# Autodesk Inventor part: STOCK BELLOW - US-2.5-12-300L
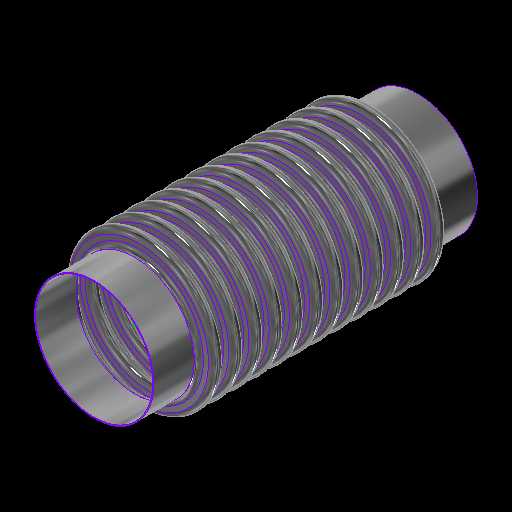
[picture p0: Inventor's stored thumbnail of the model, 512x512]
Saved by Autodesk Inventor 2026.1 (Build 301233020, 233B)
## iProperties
Category: 24 GA (0.024 THICK)
RuleStatus: InUse
Created: 2024-01
Part Number: STOCK BELLOW - US-2.5-12-300L
Project: =STOCK BELLOWS: <Stock Number><SFILL>
Material: ASTM A240-304
Description: =STOCK BELLOWS: <Stock Number>, <SID_> I.D., <SOD_> O.D., <SPLY_> PLY, <Category>, <SNET_CONS> CONS.<PITCH_><STANGENT_> TANGENT<SFILL>
Document SubType Name: Sheet Metal
Designer: GS
Stock Number: U.S-2.5-12-300L
Surface Area: 1910.87 cm^2
Volume: 57.9833 cm^3
Sheet Metal Rule: Default
Appearance: STAINLESS STEEL
Mass: 467.188 g
Density: 8.05729 g/cm^3
THK: 0.036
ID: 3.500
OD: 4.250
CONS_: 2
PITCH: 0.500
TANGENT: 0.500
BELLOWS_UPSET: 0.000
d79: 1.000
d82: 1.000
d83: 26.000
d84: 24.000
d174: 8
d214: 8
STHK_: 0.024
SID_: 2.900
SOD_: 3.700
SPITCH_: 0.500
STANGENT__: 1.000
SBELLOWS_UPSET_: 0.000
SDIFF_TAN: 1.000
d252: 2
d275: 2
d287: 0.050
d289: 0.500
d290: 0.000
SOD_NECK: 2 15/16
PLY: 1
PSET: 4.178
PBAR: 1.035
COUNTER: 1.500
NET_TUBE: 3.071
CONS: 2
S_CONS: 0
NET_CONS: 2
ID_M: 88.90 mm
OD_M: 107.95 mm
THK_M: 0.91 mm
ID_U: 3.500 in
OD_U: 4.250 in
THK_U: 0.036 in
TANGENT2: 0.500
TAN_TO_TAN: 1.000 in
d80: 2.571
d81: 10
SID: 2.375
SCONS_: 12
SPITCH: 0.250
STANGENT_: 1.000
SBELLOWS_UPSET: 0.000
SNET_CONS: 12
SS_CONS: 0
SCONS: 8
d190: 8
d191: 1
d192: 1
d193: 8
d194: 0
SIZE: 2.50
PRESSURE: 300
d230: 8
STANGENT: 4.000
SPLY_: 1
d233: 8
d234: 0
d263: 2
d265: 1
d268: 2
d269: 0
d286: 2
d288: 1
d291: 2
d292: 0
SREROLL: 0.750
BLETP: 1.000 ul
PRES_Copy: 85
MATTABLE: 20 GA (0.036 THICK)
PART_NUMBER: U.S-2.5-12-300L
PITCH_: =, <SPITCH_> PITCH,
CFILL: .
SFILL: .
MESH: ,
COMP: 0.89
EXT: 0.45
LAT: 0.52
ANG: 573
ASR: 961
LSR: 436
ANSR: 35
PRES: 300
COMPM: 8.9
EXTM: 4.45
LATM: 5.20
ASRM: 168.300
PRESM: 20.684
LSRM: 76.357
ANSRM: 6.13
TEMPMIN: 20
TEMPMAX: 800
TEMPMINM: -7
TEMPMAXM: 427
WEIGHTM: 0.467
WEIGHT: 1.030
Author: GS
Keywords: 20 GA (0.036 THICK)
Comments: =STOCK BELLOW - <STOCK NUMBER>
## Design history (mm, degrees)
sketch "Sketch2"
  geometry: L1 (0, -177.245)-(0, 562.856) reference; L2 (45.364, 0)-(44.45, 0); L3 (48.082, -2.718)-(50.343, -2.718); L4 (48.082, -3.632)-(50.343, -3.632); L5 (50.343, -9.982)-(48.082, -9.982); L6 (50.343, -9.068)-(48.082, -9.068); L7 (45.364, -12.7)-(44.45, -12.7); L8 (48.082, 0)-(48.082, -12.7); L9 (50.343, -6.35)-(53.975, -6.35); L10 (44.45, 0)-(44.45, -12.7); L11 (20.376, 102.841)-(20.376, 101.926); L12 (58.262, 457.127)-(58.262, 349.177); L13 (58.262, 444.427)-(58.262, 336.477); L14 (93.133, -58.817)-(93.133, -71.517); L15 (118.746, -66.401)-(118.746, -66.401); L16 (50.343, -9.068)-(50.343, -9.982); L17 (48.082, -9.068)-(48.082, -9.982); L18 (48.082, -9.525)-(50.343, -9.525); L19 (53.975, 0)-(53.975, -12.7); L20 (-50.343, -9.068)-(-50.343, -9.982); L21 (-50.343, -2.718)-(-48.082, -2.718); L22 (-50.343, -3.632)-(-48.082, -3.632); L23 (-48.082, -9.068)-(-50.343, -9.068); L24 (-50.343, -9.525)-(-48.082, -9.525); L25 (-48.082, -9.982)-(-50.343, -9.982); L26 (-48.082, -9.068)-(-48.082, -9.982); L27 (-44.45, 0.653)-(-44.45, -12.047); L28 (-48.082, -6.35)-(-44.45, -6.35); L29 (-50.343, 0.653)-(-50.343, -12.7); L30 (-53.061, 0)-(-53.975, 0); L31 (-53.975, 0)-(-53.975, -12.7); L32 (-53.061, -12.7)-(-53.975, -12.7); A1 r 2.718 centre (48.082, 0) between (45.364, 0) and (48.082, -2.718); A2 r 3.632 centre (48.082, 0) between (44.45, 0) and (48.082, -3.632); A3 r 3.632 centre (50.343, -6.35) between (50.343, -9.982) and (50.343, -2.718); A4 r 2.718 centre (50.343, -6.35) between (50.343, -9.068) and (50.343, -3.632); A5 r 2.718 centre (48.082, -12.7) between (48.082, -9.982) and (45.364, -12.7); A6 r 3.632 centre (48.082, -12.7) between (48.082, -9.068) and (44.45, -12.7); A7 r 3.175 centre (50.343, -6.35) between (50.343, -9.525) and (53.518, -6.35); A8 r 3.175 centre (48.082, -12.7) between (48.082, -9.525) and (44.907, -12.7); A9 r 2.718 centre (-50.343, -12.7) between (-50.343, -9.982) and (-53.061, -12.7); A10 r 2.718 centre (-48.082, -6.35) between (-48.082, -9.068) and (-48.082, -3.632); A11 r 3.175 centre (-48.082, -6.35) between (-48.082, -9.525) and (-44.907, -6.35); A12 r 3.632 centre (-48.082, -6.35) between (-48.082, -9.982) and (-48.082, -2.718); A13 r 3.175 centre (-50.343, -12.7) between (-50.343, -9.525) and (-53.518, -12.7); A14 r 3.632 centre (-50.343, -12.7) between (-50.343, -9.068) and (-53.975, -12.7); A15 r 2.718 centre (-50.343, 0) between (-53.061, 0) and (-50.343, -2.718); A16 r 3.632 centre (-50.343, 0) between (-53.975, 0) and (-50.343, -3.632); 10 further points
  constraints: 62 end point, 38 point on circle, 20 tangent, 16 centre point, 12 parallel, 9 midpoint, 7 vertical, 6 coincident, 6 concentric, 6 point on line, 4 equal radius, 4 perpendicular, 3 horizontal, 1 collinear, 1 horizontal alignment, 10 other
  dimensions: "THK" = 0.9144 distance of L11.start L11.end; "ID" = 88.9 distance of L11.end point (20.376, 13.026); "OD" = 107.95 distance of L12.start L12.end; "PITCH" = 12.7 distance of L12.start L13.start; "TANGENT" = 12.7 distance of L14.start L14.end; "BELLOWS_UPSET" = 0 distance of L15.start L15.end; "d43" = 88.9 diameter of L10 L1 (= ID); "d44" = 107.95 diameter of L9.end L1 (= OD); "d45" = 0.9144 distance between parallel lines of L5 L6 (computed from THK, PLY); "d46" = 3.6322 radius of A3 (computed from PITCH, THK, PLY); "UPSET_PITCH" = 12.7 distance of L2.end L7.end (derived); "SIDEWALL_ANGLE" = 360 deg dimension on L3 L9 (derived); "CON_GAP" = 5.4356 distance of point (48.082, -9.068) point (48.082, -3.632) (derived); "TAN1" = 4.98728 dimension on A8 (derived); "TAN2" = 4.98728 dimension on A7 (derived); "LEG1" = 2.2606 distance of L18.start L18.end (derived); "d278" = 0.9144 distance between parallel lines of L25 L23 (derived); "d279" = 3.6322 radius of A12 (derived); "d280" = 12.7 distance of L30.end L31.end (derived); "d281" = 360 deg dimension on L21 L28 (derived); "d282" = 5.4356 distance of point (-50.343, -9.068) point (-50.343, -3.632) (derived); "d283" = 4.98728 dimension on A13 (derived); "d284" = 4.98728 dimension on A11 (derived); "d285" = 2.2606 distance of L24.start L24.end (derived); "d293" = 88.9 diameter of L27 L1 (derived); "d294" = 107.95 diameter of L31 L1 (derived)
  node "Sketch Rectangular Pattern1" dims "d31" = 25.4, "ID" = 88.9
  node "Sketch Rectangular Pattern2" dims "d39" = 25.4, "PITCH" = 12.7
revolve "CONS" stored, may be unused: angle "d48" = 90 deg
node "BELLOW MIDPLANE"
pattern_linear "Rectangular Pattern2" dims "d52" = 12.7 (= UPSET_PITCH)
sketch "Sketch5"
  geometry: C1 r 45.364 at (0, 0) reference; C2 r 44.45 at (0, 0) reference
extrude "TANGENT" new body sketch "Sketch5" distance "d53" = 12.7 (= TANGENT); taper "d54" = 0 deg
revolve "SAMETAN" stored, may be unused: angle "d65" = 90 deg
revolve "DIFFTAN" stored, may be unused: angle "d70" = 90 deg
sketch "Sketch9"
  geometry: L1 (53.319, 0)-(-53.319, 0) reference; L2 (0, -17.78)-(0, 17.78) reference; L3 (38.085, 0)-(-38.085, 0); L4 (38.085, -11.906)-(38.085, 11.906); L5 (25.385, -11.906)-(25.385, 11.906); L6 (13.15, 11.906)-(13.15, -11.906); L7 (-25.385, -11.906)-(-25.385, 11.906); L8 (-38.085, -11.906)-(-38.085, 11.906); L9 (37.291, -11.906)-(37.291, 11.906); L10 (38.085, -11.906)-(37.291, -11.906); L11 (38.085, 11.906)-(37.291, 11.906); L12 (13.546, 11.906)-(12.753, 11.906); L13 (12.753, 11.906)-(12.753, -11.906); L14 (12.753, -11.906)-(13.546, -11.906); L15 (13.546, -11.906)-(13.546, 11.906); L16 (-13.546, 11.906)-(-13.546, -11.906); L17 (-13.15, 11.906)-(-13.15, -11.906); L18 (-13.546, -11.906)-(-12.753, -11.906); L19 (-12.753, -11.906)-(-12.753, 11.906); L20 (-12.753, 11.906)-(-13.546, 11.906); L21 (-38.085, -11.906)-(-37.291, -11.906); L22 (-37.291, -11.906)-(-37.291, 11.906); L23 (-37.291, 11.906)-(-38.085, 11.906); L24 (-38.085, 11.906)-(-38.085, -11.906); L25 (38.085, -0.397)-(-38.085, -0.397); L26 (-38.085, -0.397)-(-38.085, 0.397); L27 (-38.085, 0.397)-(38.085, 0.397); L28 (38.085, 0.397)-(38.085, -0.397); L29 (-38.085, 11.906)-(38.085, 11.906); L30 (38.085, 11.906)-(38.085, 12.7); L31 (38.085, 12.7)-(-38.085, 12.7); L32 (-38.085, 12.7)-(-38.085, 11.906); L33 (38.085, -11.906)-(-38.085, -11.906); L34 (-38.085, -11.906)-(-38.085, -12.7); L35 (-38.085, -12.7)-(38.085, -12.7); L36 (38.085, -12.7)-(38.085, -11.906); 30 further points
  constraints: 68 end point, 13 midpoint, 13 parallel, 8 horizontal, 7 perpendicular, 6 equal length, 3 point on line, 2 vertical, 14 other
  dimensions: "d115" = 23.8125 distance of L4.start L4.end (derived); "d116" = 12.7 distance between parallel lines of L4 L5 (derived); "d117" = 12.23516 distance between parallel lines of L5 L6 (derived); "d125" = 38.53427 distance between parallel lines of L7 L6 (derived); "d127" = 12.7 distance between parallel lines of L8 L7 (derived); "d128" = 24.93516 distance between parallel lines of L6 L4 (derived); "d130" = 76.16943 distance between parallel lines of L8 L4 (derived); "RULER_THK" = 0.79375 distance between parallel lines of L4 L9; "d135" = 0.79375 distance of L13.end L14.end (derived); "d138" = 26.29911 distance of L13.end L16.end (derived); "d143" = 0.79375 distance of L22.end L8.end (derived); "d144" = 0.79375 distance between parallel lines of L27 L25 (derived)
extrude "RULER" join sketch "Sketch9" distance "d149" = 0.79375 (derived); taper "d150" = 0 deg
extrude "BARS" join sketch "Sketch9" distance "d151" = 0.79375 (derived); taper "d152" = 0 deg
pattern_linear "Rectangular Pattern4" dims "d155" = 26.29911 (derived)
sketch "Sketch13"
  geometry: L1 (93.149, -52.467)-(93.149, -77.867); L2 (37.44, 0)-(36.83, 0); L3 (37.44, -12.7)-(36.83, -12.7); L4 (43.51, -9.83)-(40.31, -9.83); L5 (43.51, -9.22)-(40.31, -9.22); L6 (43.51, -6.35)-(46.99, -6.35); L7 (40.31, -2.87)-(43.51, -2.87); L8 (40.31, 0)-(40.31, -12.7); L9 (36.83, 0)-(36.83, -12.7); L10 (58.254, -402.451)-(58.254, -496.431); L11 (58.254, -415.151)-(58.254, -509.131); L12 (58.254, -440.551)-(58.254, -534.531); L13 (58.254, -453.251)-(58.254, -547.231); L14 (58.254, -465.951)-(58.254, -559.931); L15 (58.254, -478.651)-(58.254, -572.631); L16 (58.254, -491.351)-(58.254, -585.331); L17 (58.254, -427.851)-(58.254, -521.831); L18 (20.376, 102.536)-(20.376, 101.926); L19 (40.31, -3.48)-(43.51, -3.48); L20 (0, -722.904)-(0, 240.109) reference; L21 (-23.752, 0)-(142.514, 0) reference; A1 r 2.87 centre (40.31, 0) between (37.44, 0) and (40.31, -2.87); A2 r 2.87 centre (40.31, -12.7) between (40.31, -9.83) and (37.44, -12.7); A3 r 3.48 centre (40.31, -12.7) between (40.31, -9.22) and (36.83, -12.7); A4 r 2.87 centre (43.51, -6.35) between (43.51, -9.22) and (43.51, -3.48); A5 r 3.48 centre (43.51, -6.35) between (43.51, -9.83) and (43.51, -2.87); A6 r 3.48 centre (40.31, 0) between (36.83, 0) and (40.31, -3.48); 6 further points; 1 other entity
  constraints: 38 end point, 15 point on circle, 9 tangent, 6 centre point, 6 parallel, 5 vertical alignment, 4 point on line, 4 vertical, 3 coincident, 3 concentric, 2 collinear, 2 equal radius, 1 horizontal, 1 perpendicular, 23 other
  dimensions: "SBELLOWS_UPSET_" = 0 distance of point (118.762, -66.401) point (118.762, -66.401); "STOTAL_THK_BELLOW__" = 0.6096 distance between parallel lines of L4 L5 (derived); "d224" = 3.4798 radius of A5 (derived); "d225" = 12.7 distance of L2.end L3.end (derived); "SSIDEWALL_ANGLE_" = 0 deg angle of L7 L6 (derived); "SSCON_GAP_" = 5.7404 distance of point (40.31, -9.22) point (40.31, -3.48) (derived); "d235" = 73.66 diameter of L9 L20 (derived); "d236" = 93.98 diameter of L6.end L20 (derived)
  node "Sketch Rectangular Pattern4" dims "d228" = 25.4
  node "Sketch Rectangular Pattern5" dims "d229" = 25.4
revolve "SBELLOW" stored, may be unused: angle "d197" = 90 deg
pattern_linear "Rectangular Pattern5" dims "d204" = 12.7 (derived)
revolve "STANGENT" stored, may be unused: angle "d240" = 90 deg
revolve "SSAMETAN" stored, may be unused: angle "d241" = 90 deg
revolve "SDIFFTAN" stored, may be unused: angle "d246" = 90 deg
revolve "INVCON" stored, may be unused: angle "d295" = 90 deg
pattern_linear "Rectangular Pattern6" dims "d298" = 12.7 (derived)
revolve "INVTANGENT" stored, may be unused: angle "d302" = 90 deg
revolve "INVSAMETAN" stored, may be unused: angle "d307" = 90 deg
revolve "INVDIFFTAN" stored, may be unused: angle "d312" = 90 deg
sketch "ID BELLOW MOUNT CALC"
  geometry: L1 (44.45, 0)-(38.1, 0); L2 (38.1, 0)-(38.1, 12.7); L3 (38.1, 12.7)-(44.45, 12.7); L4 (44.45, 12.7)-(44.45, 0); L5 (36.513, 12.7)-(35.598, 12.7); L6 (35.598, 12.7)-(35.598, 0); L7 (35.598, 0)-(36.513, 0); L8 (36.513, 0)-(36.513, 12.7); L9 (0, -2.54)-(0, 15.24) reference; L10 (-8.89, 0)-(53.34, 0) reference; 1 further point
  constraints: 16 end point, 5 parallel, 2 collinear, 2 horizontal, 2 perpendicular
  dimensions: "d314" = 12.7 distance of L5.end L6.end (derived); "d315" = 0.9144 distance of L5.start L5.end (derived); "IG" = 1.5875 distance between parallel lines of L2 L8; "PIPE_OD" = 88.9 diameter of L4 L9; "PIPE_WALL" = 6.35 distance of L2.end L3.end; "ID_MT_BELLOW" = 71.1962 diameter of L6 L9 (derived)
revolve "CFILL" stored, may be unused: angle "d320" = 90 deg
pattern_linear "Rectangular Pattern7" dims "d323" = 12.7 (derived)
revolve "SFILL" stored, may be unused: angle "d324" = 90 deg
pattern_linear "Rectangular Pattern8" dims "d327" = 12.7 (derived)
node "STOCK BELLOW MIDPLANE"
node "BELLOW"
sketch "Sketch6"
  geometry: L1 (-12.7, 45.364)-(0, 45.364); L2 (0, 45.364)-(0, 44.45); L3 (0, 44.45)-(-12.7, 44.45); L4 (-12.7, 44.45)-(-12.7, 45.364); L5 (10.16, 0)-(-60.96, 0) reference; L6 (-38.1, -89.422)-(-38.1, 153.44) reference; 1 further point
  constraints: 8 end point, 2 parallel, 1 horizontal, 1 perpendicular
  dimensions: "d61" = 12.7 distance of L2.end L3.end (derived); "d62" = 0.9144 distance of L1.end L2.end (derived); "d63" = 88.9 diameter of L3 L5 (derived); "d64" = 25.4 distance between parallel lines of L4 L6 (derived)
sketch "Sketch12"
  geometry: 1 further point
sketch "Sketch14"
  geometry: L1 (-25.4, 37.44)-(0, 37.44); L2 (0, 37.44)-(0, 36.83); L3 (0, 36.83)-(-25.4, 36.83); L4 (-25.4, 36.83)-(-25.4, 37.44); L5 (5.08, 0)-(-30.48, 0) reference; L6 (0, -8.89)-(0, 53.34) reference; 1 further point
  constraints: 8 end point, 2 parallel, 1 collinear, 1 horizontal, 1 perpendicular
  dimensions: "d237" = 0.6096 distance of L3.end L1.start (derived); "d238" = 73.66 diameter of L3 L5 (derived); "d239" = 25.4 distance of L1.start L1.end (derived); "SOD_NECK" = 74.8792 diameter of L1 L5 (derived)
sketch "Sketch15"
  geometry: L1 (-8.89, 0)-(53.34, 0) reference; L2 (36.83, -152.4)-(37.44, -152.4); L3 (37.44, -152.4)-(37.44, -177.8); L4 (37.44, -177.8)-(36.83, -177.8); L5 (36.83, -177.8)-(36.83, -152.4); L6 (0, -215.9)-(0, 50.8) reference; 1 further point
  constraints: 8 end point, 2 parallel, 1 horizontal, 1 perpendicular
  dimensions: "d205" = 25.4 distance of L4.end L2.start (derived); "d206" = 0.6096 distance of L3.end L4.end (derived); "d207" = 73.66 diameter of L5 L6 (derived); "d208" = 152.4 distance between parallel lines of L1 L2 (derived)
node "TANGENT_"
node "SAME_TAN"
sketch "Sketch8"
  geometry: L1 (45.364, -25.4)-(44.45, -25.4); L2 (44.45, -25.4)-(44.45, -38.1); L3 (44.45, -38.1)-(45.364, -38.1); L4 (45.364, -38.1)-(45.364, -25.4); L5 (0, -48.26)-(0, 22.86) reference; L6 (-89.422, 0)-(153.44, 0) reference; 1 further point
  constraints: 8 end point, 2 parallel, 1 horizontal, 1 perpendicular
  dimensions: "d66" = 88.9 diameter of L2 L5 (derived); "TOTAL_THK_BELLOW" = 0.9144 distance of L2.end L3.end (derived); "d68" = 25.4 distance between parallel lines of L1 L6 (derived); "d69" = 12.7 distance of L1.end L2.end (derived)
node "DIFF_TAN"
node "Sketch Rectangular Pattern3" dims "d138" = 26.29911 (derived), "d141" = 25.4
node "SBELLOW_"
node "STANGENT_"
node "SSAME_TAN"
sketch "Sketch16"
  geometry: L1 (37.44, -152.4)-(36.83, -152.4); L2 (36.83, -152.4)-(36.83, -177.8); L3 (36.83, -177.8)-(37.44, -177.8); L4 (37.44, -177.8)-(37.44, -152.4); L5 (0, -215.9)-(0, 50.8) reference; L6 (-8.89, 0)-(53.34, 0) reference; 1 further point
  constraints: 8 end point, 2 parallel, 1 horizontal, 1 perpendicular
  dimensions: "SDIFF_TAN" = 25.4 distance of L3.end L1.start; "d243" = 0.6096 distance of L2.end L3.end (derived); "d244" = 152.4 distance between parallel lines of L1 L6 (derived); "d245" = 73.66 diameter of L2 L5 (derived)
node "SDIFF_TAN"
body "Solid15"
sketch "Sketch17"
  geometry: L1 (53.975, 12.7)-(53.061, 12.7); L2 (53.061, 12.7)-(53.061, 0); L3 (53.061, 0)-(53.975, 0); L4 (53.975, 0)-(53.975, 12.7); L5 (0, -2.54)-(0, 15.24) reference; L6 (-10.795, 0)-(64.77, 0) reference; 2 further points
  constraints: 8 end point, 2 parallel, 1 horizontal, 1 midpoint, 1 perpendicular, 1 point on line
  dimensions: "INVTANGENT" = 12.7 distance of L3.end L1.start (derived); "d300" = 0.9144 distance of L1.start L1.end (derived); "d301" = 107.95 diameter of L4 L5 (derived)
body "Solid16"
sketch "Sketch18"
  geometry: L1 (53.975, -25.4)-(53.061, -25.4); L2 (53.061, -25.4)-(53.061, -38.1); L3 (53.061, -38.1)-(53.975, -38.1); L4 (53.975, -38.1)-(53.975, -25.4); L5 (-10.795, 0)-(64.77, 0) reference; L6 (0, -48.26)-(0, 22.86) reference; 1 further point
  constraints: 8 end point, 2 parallel, 1 horizontal, 1 perpendicular
  dimensions: "d303" = 25.4 distance between parallel lines of L1 L5 (derived); "d304" = 12.7 distance of L3.end L1.start (derived); "d305" = 0.9144 distance of L2.end L3.end (derived); "d306" = 107.95 diameter of L4 L6 (derived)
body "Solid17"
sketch "Sketch19"
  geometry: L1 (53.975, -25.4)-(53.061, -25.4); L2 (53.061, -25.4)-(53.061, -38.1); L3 (53.061, -38.1)-(53.975, -38.1); L4 (53.975, -38.1)-(53.975, -25.4); L5 (0, -48.26)-(0, 22.86) reference; L6 (-10.795, 0)-(64.77, 0) reference; 1 further point
  constraints: 8 end point, 2 parallel, 1 horizontal, 1 perpendicular
  dimensions: "d308" = 12.7 distance of L1.end L2.end (derived); "d309" = 107.95 diameter of L4 L5 (derived); "d310" = 0.9144 distance of L2.end L3.end (derived); "d311" = 25.4 distance between parallel lines of L1 L6 (derived)
body "Solid18"
body "Solid19"
body "Solid20"
other parameters: "BMPL" = -76.2, "PSET" = 106.1212 (computed from OD, THK, PLY) [user parameter], "PBAR" = 26.29911 (= 0.570796 x PITCH + OD - ID) [user parameter; used in 1 equation term], "COUNTER" = 15 [user parameter], "NET_TUBE" = 77.99823 (computed from CONS_, PBAR, TANGENT) [user parameter], "S_CONS" = 0 [user parameter; used in 1 equation term], "ID_M" = 88.9 (= ID) [user parameter], "OD_M" = 107.95 (= OD) [user parameter], "THK_M" = 0.9144 (= THK) [user parameter], "ID_U" = 88.9 (= ID) [user parameter], "OD_U" = 107.95 (= OD) [user parameter], "THK_U" = 0.9144 (= THK) [user parameter], "D_UNITS" = 0 [user parameter], "TANGENT2" = 12.7 [user parameter], "TAN_TO_TAN" = 25.4 [user parameter], "OD_NECK" = 90.7288 [user parameter], "d79" = 25.4, "d80" = 65.29823 [user parameter], "d82" = 25.4, "d83" = 660.4, "d84" = 609.6, "sa_0" = 4, "FRAME_THK" = 0.79375 [user parameter], "CON_FLAT" = 12.23516 [user parameter], "SID" = 60.325 [user parameter], "SPITCH" = 6.35 [user parameter], "STANGENT_" = 25.4 [user parameter], "SBELLOWS_UPSET" = 0 [user parameter], "SS_CONS" = 0 [user parameter], "STAN_TO_TAN_" = 152.4 [user parameter], "d100" = 0.6096 [user parameter], "d191" = 25.4 [user parameter], "d194" = 0 [user parameter], "STANGENT" = 101.6 [user parameter], "d234" = 0 [user parameter], "SUPSET_PITCH_" = 12.7 [user parameter], "d269" = 0 [user parameter], "d287" = 1.27, "d289" = 12.7, "d290" = 0, "d292" = 0 [user parameter], "Thickness" = 3.048 (derived), "KFactor" = 4.4, "BendRadius" = 3.048 (derived), "BendReliefWidth" = 3.048 (derived), "BendReliefDepth" = 1.524 (derived), "CornerReliefSize" = 12.192 (derived), "SeamGap" = 0.00508, "MinimumRemnant" = 6.096 (derived), "TransitionRadius" = 3.048 (derived), "JacobiRadiusSize" = 3.048 (derived), "GapSize" = 3.048 (derived), "SREROLL" = 19.05 [user parameter], "CUR_STK_PITCH" = 12.7 [user parameter], "d328" = -76.2 (derived), "BLETP" = 1 [user parameter], "ASRM" = 1682.9993 [user parameter], "PRESM" = 206.83949 [user parameter], "LSRM" = 763.5668 [user parameter], "ANSRM" = 61.2955 [user parameter], "TEMPMIN" = 2664.83333 [user parameter], "TEMPMAX" = 6998.16667 [user parameter], "TEMPMINM" = 2664.83333 [user parameter], "TEMPMAXM" = 6998.16667 [user parameter], "WEIGHT" = 4.67188 [user parameter], "WEIGHTM" = 0.00467 [user parameter]
